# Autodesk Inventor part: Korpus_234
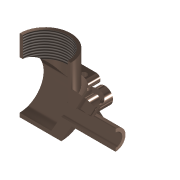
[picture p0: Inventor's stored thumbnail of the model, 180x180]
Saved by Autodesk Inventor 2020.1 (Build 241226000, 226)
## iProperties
Created: 2005-09
Part Number: Korpus_234
Document SubType Name: Modeling
Designer: F.Stasiak
Density: 1 g/cm^3
Material: Ogólny
Appearance: Brąz armatni — antyczny — polerowany
Manager: www.cadconsulting.pl
Company: Fabian Stasiak CAD Consulting
Author: F.Stasiak
Subject: Zbiór ćwiczeń. Autodesk Inventor 2020. Kurs podstawowy
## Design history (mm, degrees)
feature "Baza1"
feature "Podział1"
feature "Gwint1" dims "d0" = 8, "d1" = 0
node "Płaszczyzna konstrukcyjna1"
node "Bryła1"
node "Korpusy bryłowe"
node "Korpusy powierzchniowe"
other parameters: "d2" = 0
